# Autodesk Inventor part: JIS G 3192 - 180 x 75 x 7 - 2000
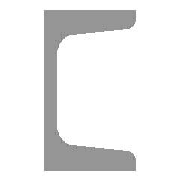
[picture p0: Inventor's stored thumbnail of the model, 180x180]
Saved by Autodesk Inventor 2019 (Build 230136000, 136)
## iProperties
_CCFamilyMember: 6
_CCFamilyDisplayName: JIS G 3192 - U 形熱間圧延鋼
_FrameMemberDoc: Frame Member File
_Version: 15.0.0
_GetPNFromCC: 1
Created: 2017-02
Part Number: JIS G 3192 - 180 x 75 x 7 - 2000
Material: 鋼、軟鋼
Description: U 形熱間圧延鋼
Document SubType Name: Modeling
Standard: JIS
Designer: shimont
Standard Revision: 2014
Standards Organization: JIS
Language: ja-JP
Size Designation: 180 x 75 x 7
Categories: <MemberInstance><Categories><Category DisplayName="形鋼" InternalName="089c4875-fa83-4c05-b084-43b9cc11f5ed" Mnemonic="GRDR"><CategoryParameter DisplayName="長さ単位ご
Stock Number: 180 x 75 x 7
Density: 7.85 g/cm^3
Appearance: 半つや出し
Mass: 42511 g
Surface Area: 12477 cm^2
Volume: 5415.42 cm^3
IsCustomPart: 1
G_L: 2000.000 mm
G_W: 75.000 mm
G_H: 180.000 mm
Author: shimont
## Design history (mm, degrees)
node "開始平面"
node "終了平面"
sketch "スケッチ"
  geometry: L1 (-21.3, 0)-(-21.3, 90); L2 (-21.3, 90)-(53.7, 90); L3 (53.7, 90)-(53.7, 87.514); L4 (48.679, 82.035)-(-4.259, 77.404); L5 (-14.3, 66.446)-(-14.3, 0); L6 (-14.3, 0)-(-21.3, 0); L7 (19.7, 90)-(19.7, 79.5); L8 (53.7, 82.475)-(53.7, 79.5); L9 (53.7, 79.5)-(19.7, 79.5); L10 (0, 15)-(0, -27); L11 (-5.539, 0)-(16.007, 0); L12 (-21.3, 0)-(-21.3, -90); L13 (-21.3, -90)-(53.7, -90); L14 (53.7, -90)-(53.7, -87.514); L15 (48.679, -82.035)-(-4.259, -77.404); L16 (-14.3, -66.446)-(-14.3, 0); L17 (0, 126)-(0, -126) reference; L18 (-36.513, 0)-(69.978, 0) reference; A1 r 11 centre (-3.3, 66.446) between (-4.259, 77.404) and (-14.3, 66.446); A2 r 11 centre (-3.3, -66.446) between (-14.3, -66.446) and (-4.259, -77.404); A3 r 5.5 centre (48.2, 87.514) between (48.679, 82.035) and (53.7, 87.514); A4 r 5.5 centre (48.2, -87.514) between (53.7, -87.514) and (48.679, -82.035); 5 further points
  constraints: 32 end point, 12 point on line, 8 point on circle, 8 tangent, 6 symmetric about line, 4 centre point, 4 parallel, 3 collinear, 3 perpendicular, 2 equal radius, 5 other
  dimensions: "d0" = 7 distance between parallel lines of L1 L5 (= G_T); "d1" = 90 distance between parallel lines of L6 L2 (= 0.5 x G_H); "d2" = 75 distance between parallel lines of L3 L1 (= G_W); "d3" = 10.5 distance of L2.end L8.end (= G_T1); "d4" = 34 distance of L7.start L2.end (= G_C); "d5" = 2.97466 distance of L8.start L8.end (computed from G_NG, G_C); "d23" = 11 radius of A1 (= G_IR); "d24" = 5.5 radius of A3 (= G_ER); "d25" = 21.3 distance between parallel lines of L10 L12 (= ey)
extrude "ボディ" new body sketch "スケッチ" stored distance "d6" = 2000 (= G_L); taper "d7" = 0 deg
node "Driven Length"
  sketch "Sketch3"
    geometry: L1 (0, 0)-(10, 0) reference
    constraints: 2 end point, 1 horizontal
  workplane "Work Plane3"
  sketch "Sketch4"
    geometry: L1 (-19.16, 0)-(14.86, 0) reference; L2 (-19.16, 2000)-(14.86, 2000) reference
    dimensions: "d29" = 2000 distance between parallel lines of L1 L2 (derived)
sketch "スケッチ5"
  geometry: L1 (0, 132.891)-(0, 0) reference; L2 (2000, 0)-(0, 0) reference; L3 (2000, 132.891)-(2000, 0) reference; L4 (2000, 132.891)-(0, 132.891) reference; L5 (0, 66.446)-(845.454, 66.446); 5 further points
  constraints: 4 point on line, 2 end point, 1 midpoint, 1 perpendicular
  dimensions: "d30" = 150 distance from line of L1 point (150, 66.446); "d31" = 300 distance of point (450, 66.446) point (150, 66.446); "d32" = 300 distance of point (750, 66.446) point (450, 66.446); "d33" = 300 distance of point (1050, 66.446) point (750, 66.446)
node "穴2"
body "Solid1"
sketch "スケッチ6"
  geometry: 4 further points
hole "穴1" sketch "スケッチ6" diameter "d35" = 33; stored, may be unused: countersink angle "d39" = 90 deg, drill point angle "d41" = 0 deg; dims "d36" = 6, "d37" = 4, "d38" = 2, "d40" = 8
other parameters: "G_W" = 75 [user parameter; used in 1 equation term], "G_H" = 180 [user parameter; used in 1 equation term], "G_T" = 7 [user parameter; used in 1 equation term], "G_T1" = 10.5 [user parameter; used in 1 equation term], "G_NG" = 0.8749 [user parameter; used in 1 equation term], "G_ER" = 5.5 [user parameter; used in 1 equation term], "G_IR" = 11 [user parameter; used in 1 equation term], "G_C" = 34 [user parameter; used in 2 equation terms], "G_L" = 2000 (= d29) [user parameter; used in 1 equation term], "ey" = 21.3 [user parameter; used in 1 equation term], "G_OFFSET_START" = 0 [user parameter; used in 1 equation term], "G_OFFSET_END" = 0 [user parameter; used in 1 equation term], "d26" = 0 (computed from G_OFFSET_START), "d28" = 90 deg
